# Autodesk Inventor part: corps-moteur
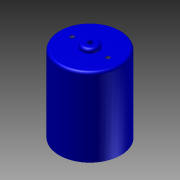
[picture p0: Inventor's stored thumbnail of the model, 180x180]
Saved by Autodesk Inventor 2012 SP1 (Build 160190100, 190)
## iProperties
Created: 2012-06
Part Number: corps-moteur
Material: Default
Document SubType Name: Modeling
Designer: Bruno
Density: 1 g/cm^3
Author: Bruno
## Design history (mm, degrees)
sketch "Esquisse1"
  geometry: C1 r 12 at (0, 0); 1 further point
  constraints: 1 centre point, 1 coincident
  dimensions: "d0" = 24 diameter of C1
extrude "Extrusion1" new body sketch "Esquisse1" distance "d1" = 30.5; taper "d2" = 0 deg
fillet "Congé1" dims "d3" = 1
sketch "Esquisse2"
  geometry: C1 r 11 at (0, 0) reference; C2 r 3.175 at (0, 0)
  constraints: 1 centre point, 1 coincident
  dimensions: "d4" = 6.35 diameter of C2
extrude "Extrusion2" join sketch "Esquisse2" distance "d5" = 1.6; taper "d6" = 0 deg
fillet "Congé2" dims "d7" = 1
sketch "Esquisse3"
  geometry: C1 r 2.175 at (0, 0) reference; C2 r 1 at (0, 0)
  constraints: 1 centre point, 1 coincident
  dimensions: "d8" = 2 diameter of C2
extrude "Extrusion3" cut sketch "Esquisse3" distance "d9" = 15; taper "d10" = 0 deg
sketch "Esquisse4"
  geometry: C1 r 3.175 at (0, 0) reference; 2 further points
  dimensions: "d11" = 14 distance of point (7, 0) point (-7, 0); "d12" = 7 distance of C1.centre point (-7, 0)
hole "Perçage1" sketch "Esquisse4" at (-7, 0), (7, 0) diameter "d13" = 1.567; stored, may be unused: countersink angle "d17" = 90 deg, drill point angle "d19" = 118 deg; dims "d14" = 6, "d15" = 4, "d16" = 2, "d18" = 8
node "Solide1"
